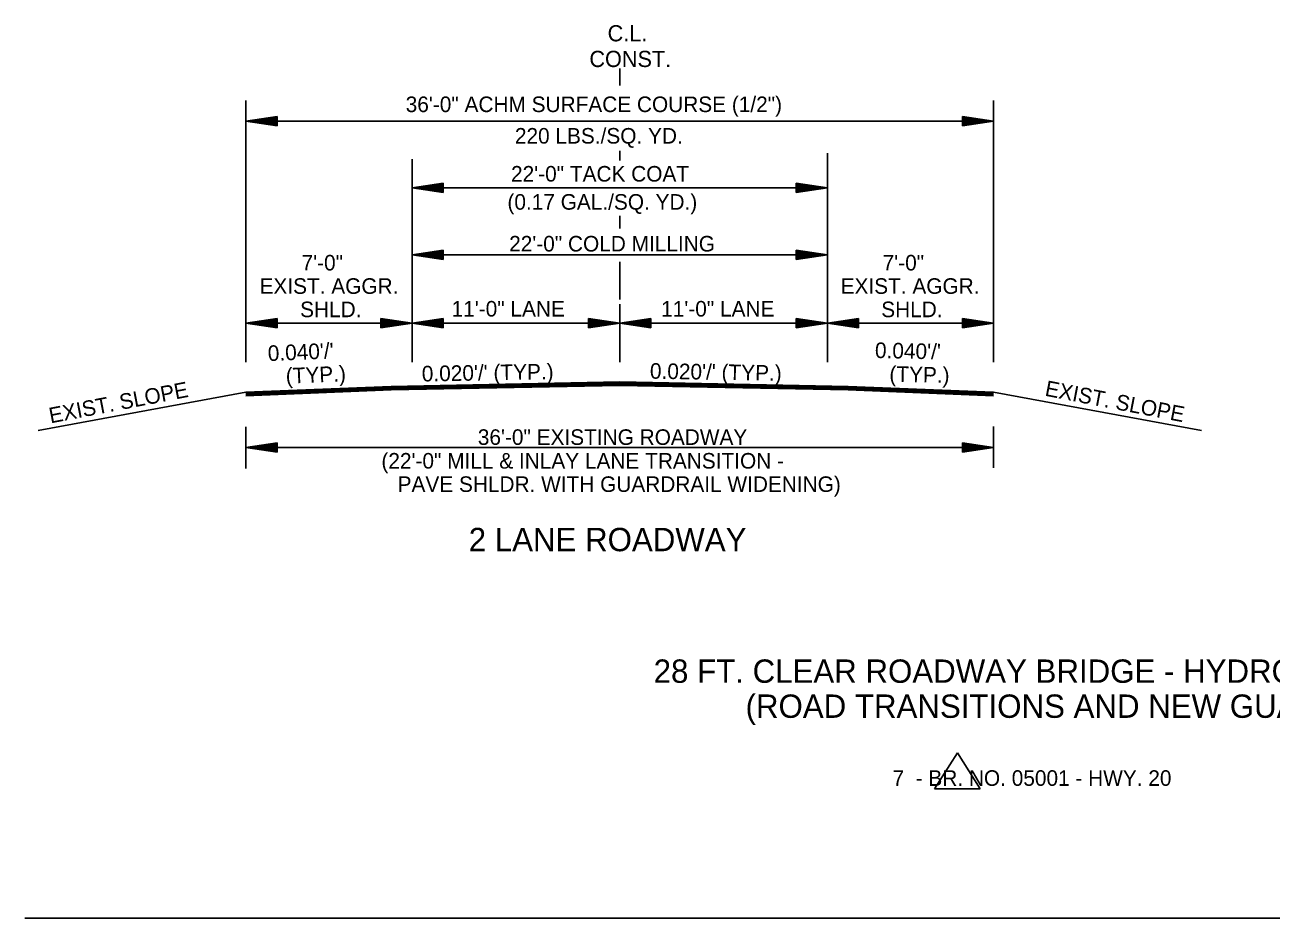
# Model space of a CAD drawing. Extents: x 544259 to 1930787, y -1961343 to 596640.
# Drawn here: x 544303 to 544903, y -1960808 to -1960378 of the extents above; entities that cross this region are included whole.
import ezdxf

# ---------------------------------------------------------------- set-up
doc = ezdxf.new("R2010")
doc.units = 0
doc.layers.add('R_Border', color=7, linetype='Continuous')
doc.layers.add('R_Draft', color=7, linetype='Continuous')

msp = doc.modelspace()

# ---------------------------------------------------------------- linework, layer by layer
at = {"layer": 'R_Border'}
for p, q in [((544479.58, -1960552.03), (544409.58, -1960554.83)), ((544479.58, -1960552.33), (544409.58, -1960555.13)), ((544699.58, -1960552.03), (544769.58, -1960554.83)), ((544699.58, -1960552.33), (544769.58, -1960555.13)), ((544479.58, -1960552.63), (544409.58, -1960555.43)), ((544479.58, -1960552.93), (544409.58, -1960555.73)), ((544479.58, -1960553.23), (544409.58, -1960556.03)), ((544479.58, -1960553.53), (544409.58, -1960556.33)), ((544479.58, -1960553.7), (544409.58, -1960556.5)), ((544699.58, -1960552.63), (544769.58, -1960555.43)), ((544699.58, -1960552.93), (544769.58, -1960555.73)), ((544699.58, -1960553.23), (544769.58, -1960556.03)), ((544699.58, -1960553.53), (544769.58, -1960556.33)), ((544699.58, -1960553.7), (544769.58, -1960556.5)), ((544752.16, -1960728.48), (544741.12, -1960745.79)), ((544763.21, -1960745.79), (544752.16, -1960728.48)), ((544741.12, -1960745.79), (544763.21, -1960745.79)), ((544303.14, -1960808.08), (545224.71, -1960808.08))]:
    msp.add_line(p, q, dxfattribs=at)
at = {"layer": 'R_Draft'}
for p, q in [((544589.58, -1960407.07), (544589.58, -1960398.89)), ((544409.58, -1960540.28), (544409.58, -1960414.32)), ((544769.58, -1960540.28), (544769.58, -1960414.32)), ((544424.58, -1960421.96), (544409.58, -1960424.21)), ((544769.58, -1960424.21), (544409.58, -1960424.21)), ((544424.58, -1960426.46), (544409.58, -1960424.21)), ((544424.58, -1960422.34), (544412.08, -1960424.21)), ((544424.58, -1960426.09), (544412.08, -1960424.21)), ((544424.58, -1960422.72), (544414.66, -1960424.21)), ((544424.58, -1960425.7), (544414.66, -1960424.21)), ((544424.58, -1960423.09), (544417.16, -1960424.21)), ((544424.58, -1960425.33), (544417.16, -1960424.21)), ((544424.58, -1960423.48), (544419.7, -1960424.21)), ((544424.58, -1960424.95), (544419.7, -1960424.21)), ((544424.58, -1960423.86), (544422.21, -1960424.21)), ((544424.58, -1960424.56), (544422.21, -1960424.21)), ((544424.58, -1960421.96), (544424.58, -1960426.46)), ((544754.58, -1960421.96), (544769.58, -1960424.21)), ((544754.58, -1960426.46), (544754.58, -1960421.96)), ((544754.58, -1960422.34), (544767.07, -1960424.21)), ((544754.58, -1960422.72), (544764.49, -1960424.21)), ((544754.58, -1960423.09), (544762, -1960424.21)), ((544754.58, -1960423.48), (544759.45, -1960424.21)), ((544754.58, -1960423.86), (544756.95, -1960424.21)), ((544754.58, -1960426.46), (544769.58, -1960424.21)), ((544754.58, -1960424.94), (544759.45, -1960424.21)), ((544754.58, -1960425.7), (544764.49, -1960424.21)), ((544754.58, -1960426.09), (544767.07, -1960424.21)), ((544754.58, -1960425.33), (544762, -1960424.21)), ((544754.58, -1960424.56), (544756.95, -1960424.21)), ((544489.58, -1960540.28), (544489.58, -1960442.58)), ((544589.58, -1960443.18), (544589.58, -1960438.56)), ((544689.58, -1960540.28), (544689.58, -1960439.66)), ((544504.58, -1960454.05), (544489.58, -1960456.3)), ((544689.58, -1960456.3), (544489.58, -1960456.3)), ((544504.58, -1960458.55), (544489.58, -1960456.3)), ((544504.58, -1960454.42), (544492.08, -1960456.3)), ((544504.58, -1960458.17), (544492.08, -1960456.3)), ((544504.58, -1960454.8), (544494.66, -1960456.3)), ((544504.58, -1960457.79), (544494.66, -1960456.3)), ((544504.58, -1960455.18), (544497.16, -1960456.3)), ((544504.58, -1960457.41), (544497.16, -1960456.3)), ((544504.58, -1960455.57), (544499.7, -1960456.3)), ((544504.58, -1960457.03), (544499.7, -1960456.3)), ((544504.58, -1960455.94), (544502.21, -1960456.3)), ((544504.58, -1960456.65), (544502.21, -1960456.3)), ((544504.58, -1960454.05), (544504.58, -1960458.55)), ((544674.58, -1960454.05), (544689.58, -1960456.3)), ((544674.58, -1960458.55), (544674.58, -1960454.05)), ((544674.58, -1960454.42), (544687.07, -1960456.3)), ((544674.58, -1960454.8), (544684.49, -1960456.3)), ((544674.58, -1960455.18), (544682, -1960456.3)), ((544674.58, -1960455.56), (544679.45, -1960456.3)), ((544674.58, -1960455.94), (544676.95, -1960456.3)), ((544674.58, -1960458.55), (544689.58, -1960456.3)), ((544674.58, -1960457.02), (544679.45, -1960456.3)), ((544674.58, -1960457.79), (544684.49, -1960456.3)), ((544674.58, -1960458.17), (544687.07, -1960456.3)), ((544674.58, -1960457.41), (544682, -1960456.3)), ((544674.58, -1960456.65), (544676.95, -1960456.3)), ((544589.58, -1960475.99), (544589.58, -1960469.83)), ((544504.58, -1960486.43), (544489.58, -1960488.68)), ((544504.58, -1960486.43), (544504.58, -1960490.93)), ((544674.58, -1960486.43), (544689.58, -1960488.68)), ((544674.58, -1960490.93), (544674.58, -1960486.43)), ((544689.58, -1960488.68), (544489.58, -1960488.68)), ((544504.58, -1960490.93), (544489.58, -1960488.68)), ((544504.58, -1960486.81), (544492.08, -1960488.68)), ((544504.58, -1960490.56), (544492.08, -1960488.68)), ((544504.58, -1960487.19), (544494.66, -1960488.68)), ((544504.58, -1960490.17), (544494.66, -1960488.68)), ((544504.58, -1960487.56), (544497.16, -1960488.68)), ((544504.58, -1960489.8), (544497.16, -1960488.68)), ((544504.58, -1960487.95), (544499.7, -1960488.68)), ((544504.58, -1960489.42), (544499.7, -1960488.68)), ((544504.58, -1960488.33), (544502.21, -1960488.68)), ((544504.58, -1960489.03), (544502.21, -1960488.68)), ((544589.58, -1960500.33), (544589.58, -1960492.06)), ((544674.58, -1960486.81), (544687.07, -1960488.68)), ((544674.58, -1960487.19), (544684.49, -1960488.68)), ((544674.58, -1960487.56), (544682, -1960488.68)), ((544674.58, -1960487.95), (544679.45, -1960488.68)), ((544674.58, -1960488.33), (544676.95, -1960488.68)), ((544674.58, -1960490.93), (544689.58, -1960488.68)), ((544674.58, -1960489.41), (544679.45, -1960488.68)), ((544674.58, -1960490.17), (544684.49, -1960488.68)), ((544674.58, -1960490.56), (544687.07, -1960488.68)), ((544674.58, -1960489.8), (544682, -1960488.68)), ((544674.58, -1960489.03), (544676.95, -1960488.68)), ((544589.58, -1960510.2), (544589.58, -1960500.33)), ((544589.58, -1960540.28), (544589.58, -1960512.33)), ((544424.58, -1960519.27), (544409.58, -1960521.52)), ((544489.58, -1960521.52), (544409.58, -1960521.52)), ((544424.58, -1960523.77), (544409.58, -1960521.52)), ((544424.58, -1960519.64), (544412.08, -1960521.52)), ((544424.58, -1960523.39), (544412.08, -1960521.52)), ((544424.58, -1960520.02), (544414.66, -1960521.52)), ((544424.58, -1960523.01), (544414.66, -1960521.52)), ((544424.58, -1960520.4), (544417.16, -1960521.52)), ((544424.58, -1960522.63), (544417.16, -1960521.52)), ((544424.58, -1960520.79), (544419.7, -1960521.52)), ((544424.58, -1960522.25), (544419.7, -1960521.52)), ((544424.58, -1960521.16), (544422.21, -1960521.52)), ((544424.58, -1960521.87), (544422.21, -1960521.52)), ((544424.58, -1960519.27), (544424.58, -1960523.77)), ((544474.58, -1960519.27), (544489.58, -1960521.52)), ((544474.58, -1960519.27), (544474.58, -1960523.77)), ((544474.58, -1960519.64), (544487.07, -1960521.52)), ((544474.58, -1960520.02), (544484.49, -1960521.52)), ((544474.58, -1960520.4), (544482, -1960521.52)), ((544474.58, -1960520.79), (544479.45, -1960521.52)), ((544474.58, -1960521.16), (544476.95, -1960521.52)), ((544474.58, -1960523.77), (544489.58, -1960521.52)), ((544474.58, -1960522.25), (544479.45, -1960521.52)), ((544474.58, -1960523.01), (544484.49, -1960521.52)), ((544474.58, -1960523.39), (544487.07, -1960521.52)), ((544474.58, -1960522.63), (544482, -1960521.52)), ((544474.58, -1960521.87), (544476.95, -1960521.52)), ((544504.58, -1960519.27), (544489.58, -1960521.52)), ((544589.58, -1960521.52), (544489.58, -1960521.52)), ((544504.58, -1960523.77), (544489.58, -1960521.52)), ((544504.58, -1960519.64), (544492.08, -1960521.52)), ((544504.58, -1960523.39), (544492.08, -1960521.52)), ((544504.58, -1960520.02), (544494.66, -1960521.52)), ((544504.58, -1960523.01), (544494.66, -1960521.52)), ((544504.58, -1960520.4), (544497.16, -1960521.52)), ((544504.58, -1960522.63), (544497.16, -1960521.52)), ((544504.58, -1960520.79), (544499.7, -1960521.52)), ((544504.58, -1960522.25), (544499.7, -1960521.52)), ((544504.58, -1960521.16), (544502.21, -1960521.52)), ((544504.58, -1960521.87), (544502.21, -1960521.52)), ((544504.58, -1960519.27), (544504.58, -1960523.77)), ((544574.58, -1960519.27), (544589.58, -1960521.52)), ((544574.58, -1960519.27), (544574.58, -1960523.77)), ((544574.58, -1960519.64), (544587.07, -1960521.52)), ((544574.58, -1960520.02), (544584.49, -1960521.52)), ((544574.58, -1960520.4), (544582, -1960521.52)), ((544574.58, -1960520.79), (544579.45, -1960521.52)), ((544574.58, -1960521.16), (544576.95, -1960521.52)), ((544574.58, -1960523.77), (544589.58, -1960521.52)), ((544574.58, -1960522.25), (544579.45, -1960521.52)), ((544574.58, -1960523.01), (544584.49, -1960521.52)), ((544574.58, -1960523.39), (544587.07, -1960521.52)), ((544574.58, -1960522.63), (544582, -1960521.52)), ((544574.58, -1960521.87), (544576.95, -1960521.52)), ((544604.58, -1960519.27), (544589.58, -1960521.52)), ((544689.58, -1960521.52), (544589.58, -1960521.52)), ((544604.58, -1960523.77), (544589.58, -1960521.52)), ((544604.58, -1960519.64), (544592.08, -1960521.52)), ((544604.58, -1960523.39), (544592.08, -1960521.52)), ((544604.58, -1960520.02), (544594.66, -1960521.52)), ((544604.58, -1960523.01), (544594.66, -1960521.52)), ((544604.58, -1960520.4), (544597.16, -1960521.52)), ((544604.58, -1960522.63), (544597.16, -1960521.52)), ((544604.58, -1960520.79), (544599.7, -1960521.52)), ((544604.58, -1960522.25), (544599.7, -1960521.52)), ((544604.58, -1960521.16), (544602.21, -1960521.52)), ((544604.58, -1960521.87), (544602.21, -1960521.52)), ((544604.58, -1960519.27), (544604.58, -1960523.77)), ((544674.58, -1960519.27), (544689.58, -1960521.52)), ((544674.58, -1960519.27), (544674.58, -1960523.77)), ((544674.58, -1960519.64), (544687.07, -1960521.52)), ((544674.58, -1960520.02), (544684.49, -1960521.52)), ((544674.58, -1960520.4), (544682, -1960521.52)), ((544674.58, -1960520.79), (544679.45, -1960521.52)), ((544674.58, -1960521.16), (544676.95, -1960521.52)), ((544674.58, -1960523.77), (544689.58, -1960521.52)), ((544674.58, -1960522.25), (544679.45, -1960521.52)), ((544674.58, -1960523.01), (544684.49, -1960521.52)), ((544674.58, -1960523.39), (544687.07, -1960521.52)), ((544674.58, -1960522.63), (544682, -1960521.52)), ((544674.58, -1960521.87), (544676.95, -1960521.52)), ((544704.58, -1960519.27), (544689.58, -1960521.52)), ((544689.58, -1960521.52), (544769.58, -1960521.52)), ((544704.58, -1960523.77), (544689.58, -1960521.52)), ((544704.58, -1960519.64), (544692.08, -1960521.52)), ((544704.58, -1960523.39), (544692.08, -1960521.52)), ((544704.58, -1960520.02), (544694.66, -1960521.52)), ((544704.58, -1960523.01), (544694.66, -1960521.52)), ((544704.58, -1960520.4), (544697.16, -1960521.52)), ((544704.58, -1960522.63), (544697.16, -1960521.52)), ((544704.58, -1960520.79), (544699.7, -1960521.52)), ((544704.58, -1960522.25), (544699.7, -1960521.52)), ((544704.58, -1960521.16), (544702.21, -1960521.52)), ((544704.58, -1960521.87), (544702.21, -1960521.52)), ((544704.58, -1960519.27), (544704.58, -1960523.77)), ((544754.58, -1960519.27), (544769.58, -1960521.52)), ((544754.58, -1960519.27), (544754.58, -1960523.77)), ((544754.58, -1960519.64), (544767.07, -1960521.52)), ((544754.58, -1960520.02), (544764.49, -1960521.52)), ((544754.58, -1960520.4), (544762, -1960521.52)), ((544754.58, -1960520.79), (544759.45, -1960521.52)), ((544754.58, -1960521.16), (544756.95, -1960521.52)), ((544754.58, -1960523.77), (544769.58, -1960521.52)), ((544754.58, -1960522.25), (544759.45, -1960521.52)), ((544754.58, -1960523.01), (544764.49, -1960521.52)), ((544754.58, -1960523.39), (544767.07, -1960521.52)), ((544754.58, -1960522.63), (544762, -1960521.52)), ((544754.58, -1960521.87), (544756.95, -1960521.52)), ((544589.58, -1960549.83), (544479.58, -1960552.03)), ((544589.58, -1960550.13), (544479.58, -1960552.33)), ((544589.58, -1960550.43), (544479.58, -1960552.63)), ((544589.58, -1960550.73), (544479.58, -1960552.93)), ((544589.58, -1960551.03), (544479.58, -1960553.23)), ((544589.58, -1960551.33), (544479.58, -1960553.53)), ((544589.58, -1960551.5), (544479.58, -1960553.7)), ((544589.58, -1960549.83), (544699.58, -1960552.03)), ((544589.58, -1960550.13), (544699.58, -1960552.33)), ((544589.58, -1960550.43), (544699.58, -1960552.63)), ((544589.58, -1960550.73), (544699.58, -1960552.93)), ((544589.58, -1960551.03), (544699.58, -1960553.23)), ((544589.58, -1960551.33), (544699.58, -1960553.53)), ((544589.58, -1960551.5), (544699.58, -1960553.7)), ((544409.58, -1960554.83), (544309.51, -1960573.2)), ((544769.58, -1960554.83), (544869.65, -1960573.2)), ((544409.58, -1960571.48), (544409.58, -1960591.48)), ((544769.58, -1960571.23), (544769.58, -1960591.23)), ((544424.58, -1960579.23), (544409.58, -1960581.48)), ((544424.58, -1960583.73), (544409.58, -1960581.48)), ((544769.58, -1960581.48), (544409.58, -1960581.48)), ((544424.58, -1960579.61), (544412.08, -1960581.48)), ((544424.58, -1960583.36), (544412.08, -1960581.48)), ((544424.58, -1960579.99), (544414.66, -1960581.48)), ((544424.58, -1960582.98), (544414.66, -1960581.48)), ((544424.58, -1960580.37), (544417.16, -1960581.48)), ((544424.58, -1960582.6), (544417.16, -1960581.48)), ((544424.58, -1960580.76), (544419.7, -1960581.48)), ((544424.58, -1960582.22), (544419.7, -1960581.48)), ((544424.58, -1960581.13), (544422.21, -1960581.48)), ((544424.58, -1960581.84), (544422.21, -1960581.48)), ((544424.58, -1960579.23), (544424.58, -1960583.73)), ((544754.58, -1960579.23), (544769.58, -1960581.48)), ((544754.58, -1960583.73), (544754.58, -1960579.23)), ((544754.58, -1960579.61), (544767.07, -1960581.48)), ((544754.58, -1960579.99), (544764.49, -1960581.48)), ((544754.58, -1960580.37), (544762, -1960581.48)), ((544754.58, -1960580.75), (544759.45, -1960581.48)), ((544754.58, -1960581.13), (544756.95, -1960581.48)), ((544754.58, -1960583.73), (544769.58, -1960581.48)), ((544754.58, -1960582.21), (544759.45, -1960581.48)), ((544754.58, -1960582.98), (544764.49, -1960581.48)), ((544754.58, -1960583.36), (544767.07, -1960581.48)), ((544754.58, -1960582.6), (544762, -1960581.48)), ((544754.58, -1960581.84), (544756.95, -1960581.48))]:
    msp.add_line(p, q, dxfattribs=at)

# ---------------------------------------------------------------- texts
for s, height, p in [('C.L.', 7.8, (544583.73, -1960385.79)), ('CONST.', 7.8, (544574.95, -1960398.16)), ('36\'-0" ACHM SURFACE COURSE (1/2")', 7.5, (544486.5, -1960419.86)), ('220 LBS./SQ. YD. ', 7.5, (544539.09, -1960435.04)), ('22\'-0" TACK COAT', 7.5, (544537.23, -1960453.33)), ('(0.17 GAL./SQ. YD.)', 7.5, (544535.49, -1960466.87)), ('22\'-0" COLD MILLING', 7.5, (544536.32, -1960487.01)), ('7\'-0"', 7.5, (544436.35, -1960496.15)), ('7\'-0"', 7.5, (544716.18, -1960496.15)), ('EXIST. AGGR.', 7.5, (544416.12, -1960507.4)), ('EXIST. AGGR.', 7.5, (544695.95, -1960507.4)), ('SHLD.', 7.5, (544435.67, -1960518.65)), ('11\'-0" LANE', 7.5, (544508.6, -1960518.34)), ('11\'-0" LANE', 7.5, (544609.52, -1960518.34)), ('SHLD.', 7.5, (544715.5, -1960518.65)), ('36\'-0" EXISTING ROADWAY', 7.5, (544521.23, -1960580.16)), ('(22\'-0" MILL & INLAY LANE TRANSITION -', 7.5, (544474.81, -1960591.57)), ('PAVE SHLDR. WITH GUARDRAIL WIDENING)', 7.5, (544482.61, -1960602.82)), ('2 LANE ROADWAY', 11.25, (544516.85, -1960631.37)), ('28 FT. CLEAR ROADWAY BRIDGE - HYDRODEMOLITION', 11.25, (544605.91, -1960694.76)), ('(ROAD TRANSITIONS AND NEW GUARDRAIL)', 11.25, (544650.16, -1960711.63)), ('      7  - BR. NO. 05001 - HWY. 20', 7.5, (544704.22, -1960744.38))]:
    msp.add_text(s, height=height, dxfattribs=at).set_placement(p)
for s, rotation, p in [("  0.040'/'", 2.44797, (544414.68, -1960540.05)), ("0.040'/'", 358.68162, (544712.41, -1960538.27)), (' (TYP.)', 2.44797, (544426.11, -1960550.82)), ("0.020'/' (TYP.)", 0.97192, (544494.32, -1960549.62)), ("0.020'/' (TYP.)", 359.02808, (544604.06, -1960548.25)), ('(TYP.)', 358.68162, (544719.35, -1960549.69)), ('EXIST. SLOPE', 10.88286, (544315.49, -1960569.82)), ('EXIST. SLOPE', 349.11714, (544793.96, -1960556.42))]:
    msp.add_text(s, height=7.5, rotation=rotation, dxfattribs=at).set_placement(p)

doc.saveas('drawing.dxf')
